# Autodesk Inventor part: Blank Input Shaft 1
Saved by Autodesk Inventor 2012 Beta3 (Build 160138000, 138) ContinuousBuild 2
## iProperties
Created: 2011-01
Part Number: Blank Input Shaft 1
Material: Steel
Document SubType Name: Modeling
Designer: Beta-8540w
Density: 1 g/cm^3
CustomPartVersion: 1
Author: Beta-8540w
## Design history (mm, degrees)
sketch "Main Sketch"
  geometry: L1 (0, 0)-(43, 0) reference; L2 (0, 0)-(0, 45); L3 (12, 45)-(12, 6); L4 (0, 45)-(12, 45); L5 (15, 6)-(15, 5); L6 (12, 6)-(15, 6); L7 (43, 5)-(43, 0); L8 (15, 5)-(43, 5)
  constraints: 16 end point, 5 horizontal, 4 vertical
  dimensions: "d3" = 90 diameter of L4 L1 (derived); "d4" = 12 diameter of L6 L1 (derived); "d5" = 10 diameter of L8 L1 (derived)
revolve "Revolution1" sketch "Main Sketch" stored, may be unused: angle "d6" = 0 deg
chamfer "Chamfer1" distance "d7" = 0.5; stored, may be unused: second distance "d8" = 0.125, angle "d9" = 45 deg
node "Retaining Ring Groove1"
body "Solid1"
feature "iFeature27:1"
other parameters: "d0" = 0, "d1" = 0, "d2" = 0
